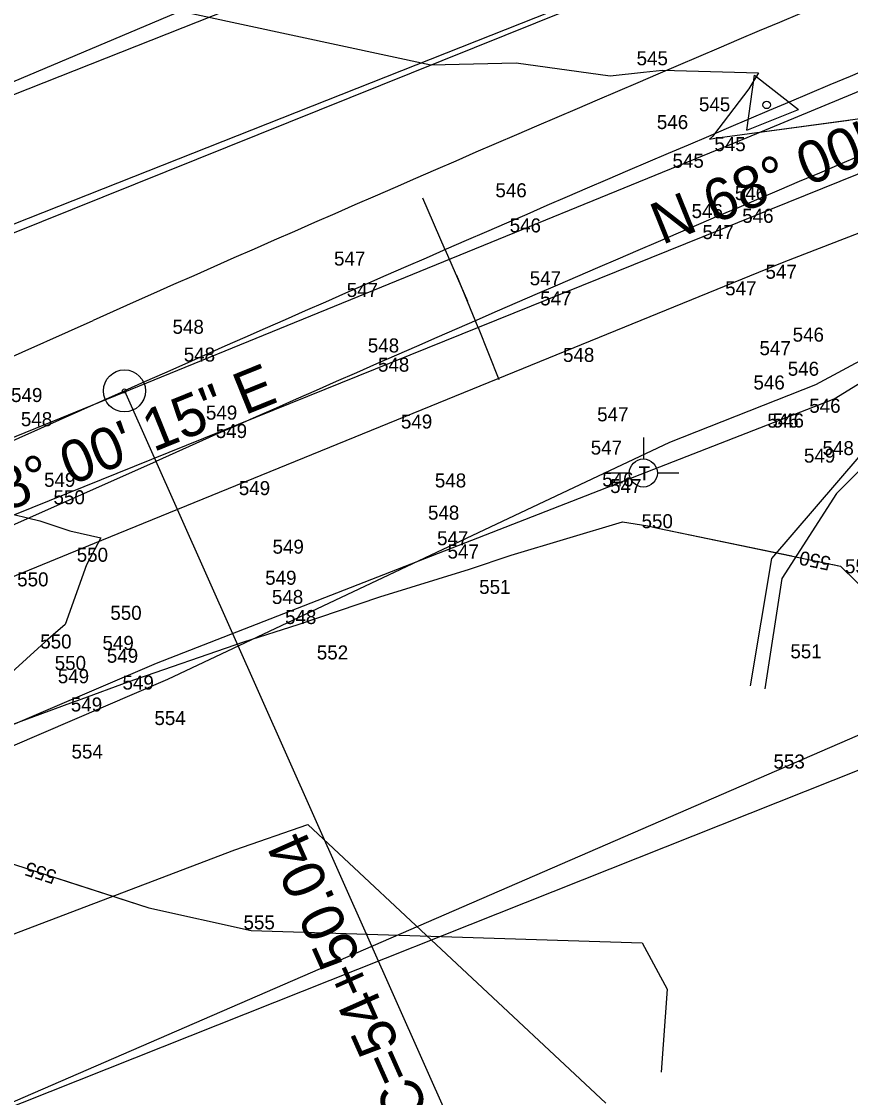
# Model space of a CAD drawing. Extents: x 1787461 to 1970323, y 938412 to 1118748.
# Drawn here: x 1967168 to 1967286.2, y 1117535 to 1117688.4 of the extents above; entities that cross this region are included whole.
import ezdxf

# ---------------------------------------------------------------- set-up
doc = ezdxf.new("R2010")
doc.units = 0
for name, color, linetype in [('Default', 7, 'Continuous'), ('HHA ADDITIONAL XSs', 7, 'Continuous'), ('Level 1', 7, 'Continuous'), ('RD_EX_Driveway', 7, 'Continuous'), ('RD_EX_DV_Prop', 7, 'Continuous'), ('RD_EX_Fence_Other', 7, 'Continuous'), ('RD_EX_Road', 7, 'Continuous'), ('RD_EX_UT', 7, 'Continuous'), ('RD_EX_VEG', 7, 'Continuous'), ('RD_HC_CL', 7, 'Continuous'), ('RD_HC_CL_Rel', 7, 'Continuous'), ('RD_HC_Data', 7, 'Continuous'), ('RD_HC_Data_Rel', 7, 'Continuous'), ('RD_HC_Data_Tic', 7, 'Continuous'), ('RD_HC_Data_Tic_Rel', 7, 'Continuous'), ('RD_PD_Final_TrvlWay', 7, 'Continuous')]:
    doc.layers.add(name, color=color, linetype=linetype)

msp = doc.modelspace()

# ---------------------------------------------------------------- linework, layer by layer
at = {"layer": 'Default'}
for points in [[(1967109.17, 1117712.29), (1967121.66, 1117711.15), (1967136.36, 1117707.16), (1967187.23, 1117690.58), (1967226.39, 1117682.18), (1967238.58, 1117682.48), (1967251.98, 1117680.61), (1967256.69, 1117681.12), (1967259.41, 1117681.41), (1967273.1, 1117681.06), (1967271.73, 1117678.76), (1967266.71, 1117672.16), (1967266.53, 1117671.99), (1967266.14, 1117671.61), (1967266.88, 1117671.73), (1967270.77, 1117672.26), (1967285.98, 1117674.31)], [(1967109.17, 1117712.29), (1967121.66, 1117711.15), (1967136.36, 1117707.16), (1967187.23, 1117690.58), (1967226.39, 1117682.18), (1967238.58, 1117682.48), (1967251.98, 1117680.61), (1967256.69, 1117681.12), (1967259.41, 1117681.41), (1967273.1, 1117681.06), (1967271.73, 1117678.76), (1967266.71, 1117672.16), (1967266.53, 1117671.99), (1967266.14, 1117671.61), (1967266.88, 1117671.73), (1967270.77, 1117672.26), (1967285.98, 1117674.31)], [(1967109.17, 1117712.29), (1967121.66, 1117711.15), (1967136.36, 1117707.16), (1967187.23, 1117690.58), (1967226.39, 1117682.18), (1967238.58, 1117682.48), (1967251.98, 1117680.61), (1967256.69, 1117681.12), (1967259.41, 1117681.41), (1967273.1, 1117681.06), (1967271.73, 1117678.76), (1967266.71, 1117672.16), (1967266.53, 1117671.99), (1967266.14, 1117671.61), (1967266.88, 1117671.73), (1967270.77, 1117672.26), (1967285.98, 1117674.31)], [(1967109.17, 1117712.29), (1967121.66, 1117711.15), (1967136.36, 1117707.16), (1967187.23, 1117690.58), (1967226.39, 1117682.18), (1967238.58, 1117682.48), (1967251.98, 1117680.61), (1967256.69, 1117681.12), (1967259.41, 1117681.41), (1967273.1, 1117681.06), (1967271.73, 1117678.76), (1967266.71, 1117672.16), (1967266.53, 1117671.99), (1967266.14, 1117671.61), (1967266.88, 1117671.73), (1967270.77, 1117672.26), (1967285.98, 1117674.31)], [(1967109.17, 1117712.29), (1967121.66, 1117711.15), (1967136.36, 1117707.16), (1967187.23, 1117690.58), (1967226.39, 1117682.18), (1967238.58, 1117682.48), (1967251.98, 1117680.61), (1967256.69, 1117681.12), (1967259.41, 1117681.41), (1967273.1, 1117681.06), (1967271.73, 1117678.76), (1967266.71, 1117672.16), (1967266.53, 1117671.99), (1967266.14, 1117671.61), (1967266.88, 1117671.73), (1967270.77, 1117672.26), (1967285.98, 1117674.31)], [(1967109.17, 1117712.29), (1967121.66, 1117711.15), (1967136.36, 1117707.16), (1967187.23, 1117690.58), (1967226.39, 1117682.18), (1967238.58, 1117682.48), (1967251.98, 1117680.61), (1967256.69, 1117681.12), (1967259.41, 1117681.41), (1967273.1, 1117681.06), (1967271.73, 1117678.76), (1967266.71, 1117672.16), (1967266.53, 1117671.99), (1967266.14, 1117671.61), (1967266.88, 1117671.73), (1967270.77, 1117672.26), (1967285.98, 1117674.31)], [(1967187.23, 1117690.58), (1967226.39, 1117682.18), (1967238.58, 1117682.48), (1967251.98, 1117680.61), (1967256.69, 1117681.12), (1967259.41, 1117681.41), (1967273.1, 1117681.06), (1967271.73, 1117678.76), (1967266.71, 1117672.16), (1967266.53, 1117671.99), (1967266.14, 1117671.61), (1967266.88, 1117671.73), (1967270.77, 1117672.26), (1967292.51, 1117675.18)], [(1967165.16, 1117618.5), (1967170.66, 1117617.16), (1967174.94, 1117615.74), (1967179.34, 1117614.75), (1967177.32, 1117610.89), (1967174.24, 1117602.41), (1967172.56, 1117600.93), (1967171.42, 1117599.91), (1967166.07, 1117595.09)], [(1967165.16, 1117618.5), (1967170.66, 1117617.16), (1967174.94, 1117615.74), (1967179.34, 1117614.75), (1967177.32, 1117610.89), (1967174.24, 1117602.41), (1967172.56, 1117600.93), (1967171.42, 1117599.91), (1967166.07, 1117595.09)], [(1967165.16, 1117618.5), (1967170.66, 1117617.16), (1967174.94, 1117615.74), (1967179.34, 1117614.75), (1967177.32, 1117610.89), (1967174.24, 1117602.41), (1967172.56, 1117600.93), (1967171.42, 1117599.91), (1967166.07, 1117595.09)], [(1967165.16, 1117618.5), (1967170.66, 1117617.16), (1967174.94, 1117615.74), (1967179.34, 1117614.75), (1967177.32, 1117610.89), (1967174.24, 1117602.41), (1967172.56, 1117600.93), (1967171.42, 1117599.91), (1967166.07, 1117595.09)], [(1967165.16, 1117618.5), (1967170.66, 1117617.16), (1967174.94, 1117615.74), (1967179.34, 1117614.75), (1967177.32, 1117610.89), (1967174.24, 1117602.41), (1967172.56, 1117600.93), (1967171.42, 1117599.91), (1967166.07, 1117595.09)], [(1967165.16, 1117618.5), (1967170.66, 1117617.16), (1967174.94, 1117615.74), (1967179.34, 1117614.75), (1967177.32, 1117610.89), (1967174.24, 1117602.41), (1967172.56, 1117600.93), (1967171.42, 1117599.91), (1967166.07, 1117595.09)], [(1967165.16, 1117618.5), (1967170.66, 1117617.16), (1967174.94, 1117615.74), (1967179.34, 1117614.75), (1967177.32, 1117610.89), (1967174.24, 1117602.41), (1967172.56, 1117600.93), (1967171.42, 1117599.91), (1967166.07, 1117595.09)], [(1967161.37, 1117586.18), (1967175.08, 1117591.23), (1967176.56, 1117591.75), (1967183.26, 1117594.21), (1967199.73, 1117599.91), (1967207.48, 1117602.37), (1967219.12, 1117606.34), (1967231.92, 1117610.29), (1967237.86, 1117612.28), (1967253.72, 1117617.02), (1967257.35, 1117616.45), (1967258.74, 1117616.11), (1967284.82, 1117610.72), (1967289.39, 1117606.2), (1967296.77, 1117598.7), (1967299.3, 1117593.67), (1967306.99, 1117580.97), (1967306.62, 1117576.04)], [(1967161.37, 1117586.18), (1967175.08, 1117591.23), (1967176.56, 1117591.75), (1967183.26, 1117594.21), (1967199.73, 1117599.91), (1967207.48, 1117602.37), (1967219.12, 1117606.34), (1967231.92, 1117610.29), (1967237.86, 1117612.28), (1967253.72, 1117617.02), (1967257.35, 1117616.45), (1967258.74, 1117616.11), (1967277.85, 1117612.16)], [(1967161.37, 1117586.18), (1967175.08, 1117591.23), (1967176.56, 1117591.75), (1967183.26, 1117594.21), (1967199.73, 1117599.91), (1967207.48, 1117602.37), (1967219.12, 1117606.34), (1967231.92, 1117610.29), (1967237.86, 1117612.28), (1967253.72, 1117617.02), (1967257.35, 1117616.45), (1967258.74, 1117616.11), (1967277.85, 1117612.16)], [(1967161.37, 1117586.18), (1967175.08, 1117591.23), (1967176.56, 1117591.75), (1967183.26, 1117594.21), (1967199.73, 1117599.91), (1967207.48, 1117602.37), (1967219.12, 1117606.34), (1967231.92, 1117610.29), (1967237.86, 1117612.28), (1967253.72, 1117617.02), (1967257.35, 1117616.45), (1967258.74, 1117616.11), (1967277.85, 1117612.16)], [(1967161.37, 1117586.18), (1967175.08, 1117591.23), (1967176.56, 1117591.75), (1967183.26, 1117594.21), (1967199.73, 1117599.91), (1967207.48, 1117602.37), (1967219.12, 1117606.34), (1967231.92, 1117610.29), (1967237.86, 1117612.28), (1967253.72, 1117617.02), (1967257.35, 1117616.45), (1967258.74, 1117616.11), (1967277.85, 1117612.16)], [(1967161.37, 1117586.18), (1967175.08, 1117591.23), (1967176.56, 1117591.75), (1967183.26, 1117594.21), (1967199.73, 1117599.91), (1967207.48, 1117602.37), (1967219.12, 1117606.34), (1967231.92, 1117610.29), (1967237.86, 1117612.28), (1967253.72, 1117617.02), (1967257.35, 1117616.45), (1967258.74, 1117616.11), (1967277.85, 1117612.16)], [(1967161.37, 1117586.18), (1967175.08, 1117591.23), (1967176.56, 1117591.75), (1967183.26, 1117594.21), (1967199.73, 1117599.91), (1967207.48, 1117602.37), (1967219.12, 1117606.34), (1967231.92, 1117610.29), (1967237.86, 1117612.28), (1967253.72, 1117617.02), (1967257.35, 1117616.45), (1967258.74, 1117616.11), (1967277.85, 1117612.16)], [(1967283.72, 1117610.95), (1967284.82, 1117610.72), (1967289.39, 1117606.2), (1967296.77, 1117598.7), (1967299.3, 1117593.67), (1967306.99, 1117580.97), (1967306.62, 1117576.04)], [(1967283.72, 1117610.95), (1967284.82, 1117610.72), (1967289.39, 1117606.2), (1967296.77, 1117598.7), (1967299.3, 1117593.67), (1967306.99, 1117580.97), (1967306.62, 1117576.04)], [(1967283.72, 1117610.95), (1967284.82, 1117610.72), (1967289.39, 1117606.2), (1967296.77, 1117598.7), (1967299.3, 1117593.67), (1967306.99, 1117580.97), (1967306.62, 1117576.04)], [(1967283.72, 1117610.95), (1967284.82, 1117610.72), (1967289.39, 1117606.2), (1967296.77, 1117598.7), (1967299.3, 1117593.67), (1967306.99, 1117580.97), (1967306.62, 1117576.04)], [(1967283.72, 1117610.95), (1967284.82, 1117610.72), (1967289.39, 1117606.2), (1967296.77, 1117598.7), (1967299.3, 1117593.67), (1967306.99, 1117580.97), (1967306.62, 1117576.04)], [(1967283.72, 1117610.95), (1967284.82, 1117610.72), (1967289.39, 1117606.2), (1967296.77, 1117598.7), (1967299.3, 1117593.67), (1967306.99, 1117580.97), (1967306.62, 1117576.04)], [(1967148, 1117574.3), (1967186.2, 1117562), (1967200.76, 1117558.78), (1967256.52, 1117557), (1967260.1, 1117550.41), (1967259.21, 1117538.57)], [(1967173.25, 1117566.17), (1967186.2, 1117562), (1967200.76, 1117558.78), (1967256.52, 1117557), (1967260.1, 1117550.41), (1967259.21, 1117538.57)], [(1967173.25, 1117566.17), (1967186.2, 1117562), (1967200.76, 1117558.78), (1967256.52, 1117557), (1967260.1, 1117550.41), (1967259.21, 1117538.57)], [(1967173.25, 1117566.17), (1967186.2, 1117562), (1967200.76, 1117558.78), (1967256.52, 1117557), (1967260.1, 1117550.41), (1967259.21, 1117538.57)], [(1967173.25, 1117566.17), (1967186.2, 1117562), (1967200.76, 1117558.78), (1967256.52, 1117557), (1967260.1, 1117550.41), (1967259.21, 1117538.57)], [(1967173.25, 1117566.17), (1967186.2, 1117562), (1967200.76, 1117558.78), (1967256.52, 1117557), (1967260.1, 1117550.41), (1967259.21, 1117538.57)], [(1967173.25, 1117566.17), (1967186.2, 1117562), (1967200.76, 1117558.78), (1967256.52, 1117557), (1967260.1, 1117550.41), (1967259.21, 1117538.57)]]:
    msp.add_lwpolyline(points, dxfattribs=at)
at = {"layer": 'HHA ADDITIONAL XSs'}
for points in [[(1969266.55, 1117963.61), (1967907.56, 1117966.55), (1967403.98, 1117771.66), (1967075.57, 1117641.84)], [(1969308.89, 1117819.66), (1967912.94, 1117853.44), (1967442.55, 1117653.93), (1967107.32, 1117508.48)]]:
    msp.add_lwpolyline(points, dxfattribs=at)
at = {"layer": 'Level 1'}
for points in [[(1968647.29, 1117975.82), (1967967.92, 1117975.82), (1967727.47, 1117916.63), (1966985.13, 1117603.01)], [(1968654.57, 1117840.68), (1968058.24, 1117848.48), (1967686.38, 1117740.3), (1966964.76, 1117453.35)]]:
    msp.add_lwpolyline(points, dxfattribs=at)
at = {"layer": 'RD_EX_Driveway'}
msp.add_lwpolyline([(1967307.6, 1117666.03), (1967312.88, 1117658.05), (1967312.4, 1117654.22), (1967308.84, 1117649.01), (1967296.51, 1117633.35), (1967284.22, 1117621.05), (1967276.43, 1117608.93), (1967274.02, 1117593.22)], dxfattribs=at)
at = {"layer": 'RD_EX_DV_Prop'}
msp.add_line((1966769.51, 1117457.48), (1967696.84, 1117832.06), dxfattribs=at)
at = {"layer": 'RD_EX_Fence_Other'}
for points in [[(1966803.22, 1117549.06), (1966808.8, 1117506.9), (1966864.07, 1117525.43), (1966962.8, 1117571.4), (1967060.23, 1117612.78), (1967157.77, 1117654.58), (1967254.5, 1117693.48), (1967317.6, 1117718.63)], [(1967260.47, 1117628.39), (1967281.3, 1117636.63), (1967309.11, 1117651.56), (1967274.94, 1117611.82), (1967271.94, 1117593.66)], [(1966879.09, 1117474.94), (1966985.88, 1117513.17), (1967082.44, 1117548.84), (1967188.89, 1117594.6), (1967260.47, 1117628.39)], [(1966814.04, 1117405.76), (1966802.15, 1117419.77), (1966805.19, 1117443.48), (1966993.4, 1117492.9), (1967087.17, 1117527.94), (1967198.46, 1117570.29), (1967208.88, 1117573.86), (1967251.36, 1117534.17)]]:
    msp.add_lwpolyline(points, dxfattribs=at)
at = {"layer": 'RD_EX_Road'}
for points in [[(1966768.28, 1117466.83), (1966868.93, 1117506.7), (1966969.96, 1117548.31), (1967069.86, 1117589.6), (1967171.37, 1117630.89), (1967269.56, 1117671.02), (1967319.89, 1117691.93), (1967370.29, 1117712.23), (1967469.03, 1117750.91), (1967565.44, 1117788.86), (1967660.02, 1117826.88), (1967693.17, 1117840.55), (1967696.66, 1117832.16)], [(1966774.52, 1117449.93), (1966874.96, 1117489.75), (1966977.23, 1117531.51), (1967077.03, 1117572.42), (1967179.47, 1117614.42), (1967276.75, 1117654.08), (1967307.6, 1117666.03)]]:
    msp.add_lwpolyline(points, dxfattribs=at)
at = {"layer": 'RD_EX_UT'}
for p, q in [((1967256.69, 1117629.06), (1967256.69, 1117625.99)), ((1967251.76, 1117624.01), (1967254.69, 1117624.01)), ((1967258.69, 1117624.01), (1967261.76, 1117624.01))]:
    msp.add_line(p, q, dxfattribs=at)
msp.add_circle((1967256.69, 1117623.99), 2, dxfattribs=at)
at = {"layer": 'RD_EX_VEG'}
for points in [[(1966803.22, 1117549.06), (1966801.85, 1117502.56), (1966864.07, 1117525.43), (1966961.82, 1117572.79), (1967059.09, 1117613.38), (1967156.27, 1117655.27), (1967254.08, 1117694.01), (1967316.99, 1117719.5)], [(1966832.92, 1117460.39), (1966879.09, 1117474.94), (1966985, 1117515.6), (1967082.35, 1117552.01), (1967187.28, 1117596.9), (1967283.89, 1117634.57), (1967305.16, 1117647.66)]]:
    msp.add_lwpolyline(points, dxfattribs=at)
at = {"layer": 'RD_HC_CL'}
msp.add_line((1966769.51, 1117457.48), (1967848.24, 1117893.22), dxfattribs=at)
at = {"layer": 'RD_HC_CL_Rel'}
msp.add_line((1967000.16, 1117554.42), (1967182.71, 1117635.7), dxfattribs=at)
msp.add_arc((1969513.16, 1112401.48), 5729.58, 111.995838, 114.000153, dxfattribs=at)
at = {"layer": 'RD_HC_Data_Rel'}
for p, q in [((1967271.45, 1117672.86), (1967272.56, 1117680.72)), ((1967272.56, 1117680.72), (1967278.81, 1117675.83)), ((1967271.45, 1117672.86), (1967278.81, 1117675.83)), ((1967182.71, 1117635.7), (1967243.3, 1117499.62))]:
    msp.add_line(p, q, dxfattribs=at)
for centre, radius in [((1967274.27, 1117676.47), 0.529), ((1967182.71, 1117635.7), 3), ((1967182.71, 1117635.7), 0.282)]:
    msp.add_circle(centre, radius, dxfattribs=at)
at = {"layer": 'RD_HC_Data_Tic'}
for q in [(1967230.12, 1117652.16), (1967236.11, 1117637.33)]:
    msp.add_line((1967233.12, 1117644.74), q, dxfattribs=at)
at = {"layer": 'RD_HC_Data_Tic_Rel'}
for q in [(1967225.25, 1117663.16), (1967231.63, 1117648.49)]:
    msp.add_line((1967228.44, 1117655.82), q, dxfattribs=at)
at = {"layer": 'RD_PD_Final_TrvlWay'}
for p, q in [((1966995.68, 1117564.47), (1967178.24, 1117645.75)), ((1967004.63, 1117544.37), (1967187.19, 1117625.65))]:
    msp.add_line(p, q, dxfattribs=at)
for radius, start, end in [(5740.58, 111.995838, 114.000153), (5718.58, 111.99584, 114.00015)]:
    msp.add_arc((1969513.16, 1112401.48), radius, start, end, dxfattribs=at)

# ---------------------------------------------------------------- texts
at = {"layer": 'Default'}
for s, p in [('545', (1967255.73, 1117682.12)), ('545', (1967264.62, 1117675.56)), ('546', (1967258.62, 1117673.03)), ('545', (1967266.82, 1117669.88)), ('545', (1967260.85, 1117667.51)), ('546', (1967235.6, 1117663.3)), ('546', (1967269.74, 1117662.9)), ('546', (1967263.57, 1117660.34)), ('546', (1967270.79, 1117659.66)), ('546', (1967237.63, 1117658.3)), ('547', (1967265.12, 1117657.34)), ('547', (1967212.59, 1117653.57)), ('547', (1967274.11, 1117651.69)), ('547', (1967240.49, 1117650.76)), ('547', (1967214.4, 1117649.09)), ('547', (1967268.36, 1117649.33)), ('547', (1967241.99, 1117647.89)), ('548', (1967189.57, 1117643.84)), ('546', (1967277.98, 1117642.72)), ('548', (1967217.41, 1117641.18)), ('547', (1967273.25, 1117640.79)), ('548', (1967191.17, 1117639.88)), ('548', (1967245.24, 1117639.83)), ('548', (1967218.86, 1117638.44)), ('546', (1967277.28, 1117637.86)), ('546', (1967272.39, 1117635.9)), ('549', (1967166.55, 1117634.11)), ('549', (1967194.33, 1117631.6)), ('546', (1967280.35, 1117632.58)), ('548', (1967167.95, 1117630.67)), ('549', (1967222.13, 1117630.33)), ('547', (1967250.11, 1117631.36)), ('546', (1967274.37, 1117630.46)), ('546', (1967275.13, 1117630.48)), ('549', (1967195.73, 1117628.98)), ('547', (1967249.19, 1117626.62)), ('549', (1967279.59, 1117625.47)), ('548', (1967282.24, 1117626.54)), ('549', (1967171.25, 1117622.02)), ('549', (1967199.02, 1117620.84)), ('548', (1967226.97, 1117621.93)), ('546', (1967250.83, 1117622.08)), ('547', (1967251.96, 1117621.14)), ('550', (1967172.6, 1117619.53)), ('548', (1967225.99, 1117617.34)), ('550', (1967256.44, 1117616.12)), ('547', (1967227.28, 1117613.7)), ('549', (1967203.83, 1117612.49)), ('547', (1967228.78, 1117611.8)), ('550', (1967175.91, 1117611.34)), ('550', (1967285.44, 1117609.7)), ('550', (1967167.42, 1117607.83)), ('549', (1967202.78, 1117608.06)), ('548', (1967203.74, 1117605.32)), ('551', (1967233.29, 1117606.76)), ('550', (1967180.7, 1117603.06)), ('548', (1967205.61, 1117602.46)), ('550', (1967170.71, 1117598.97)), ('549', (1967179.58, 1117598.77)), ('549', (1967180.2, 1117596.94)), ('552', (1967210.14, 1117597.41)), ('551', (1967277.66, 1117597.57)), ('550', (1967172.77, 1117595.91)), ('549', (1967173.21, 1117594.02)), ('549', (1967182.44, 1117593.12)), ('549', (1967175.07, 1117589.99)), ('554', (1967186.99, 1117588.06)), ('554', (1967175.17, 1117583.28)), ('553', (1967275.25, 1117581.86)), ('555', (1967199.69, 1117558.93))]:
    msp.add_text(s, height=2, dxfattribs=at).set_placement(p)
for s, rotation, p in [('550', 168.329, (1967283.54, 1117612.01)), ('550', 168.329, (1967283.54, 1117612.01)), ('550', 168.329, (1967283.54, 1117612.01)), ('550', 168.329, (1967283.54, 1117612.01)), ('550', 168.329, (1967283.54, 1117612.01)), ('550', 168.329, (1967283.54, 1117612.01)), ('555', 162.1535, (1967173.18, 1117567.24)), ('555', 162.1535, (1967173.18, 1117567.24)), ('555', 162.1535, (1967173.18, 1117567.24)), ('555', 162.1535, (1967173.18, 1117567.24)), ('555', 162.1535, (1967173.18, 1117567.24)), ('555', 162.1535, (1967173.18, 1117567.24))]:
    msp.add_text(s, height=2, rotation=rotation, dxfattribs=at).set_placement(p)
at = {"layer": 'RD_EX_UT'}
msp.add_text('T', height=2, dxfattribs=at).set_placement((1967256.02, 1117622.95))
at = {"layer": 'RD_HC_Data'}
for p in [(1967259.35, 1117656.47), (1967154.33, 1117613.81)]:
    msp.add_text('N 68%%d 00\' 15" E', height=6, rotation=21.9958, dxfattribs=at).set_placement(p)
at = {"layer": 'RD_HC_Data_Rel'}
msp.add_text('RELOC. PC=54+50.04', height=6, rotation=114.0002, dxfattribs=at).set_placement((1967241.51, 1117498.8))

doc.saveas('drawing.dxf')
